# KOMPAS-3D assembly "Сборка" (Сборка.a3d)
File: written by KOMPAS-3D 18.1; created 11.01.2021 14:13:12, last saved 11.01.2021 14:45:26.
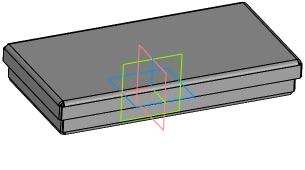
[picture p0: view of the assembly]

Document properties: Полное имя файла: D:\Ящик\Сборка.a3d

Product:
- Part/product: Сборка
    Масса: 0.773946
  - Component [detail]: Ящик  | designation 001  | Масса: 0.424246; Форматы листов документа: A3; source file: 001 - Ящик.m3d, Развертки.cdw
  - Component [detail]: Крышка  | designation 002  | Масса: 0.3497; Форматы листов документа: A3; source file: 002 - Крышка.m3d, Развертки.cdw

Referenced files in D:\Ящик\: 001 - Ящик.m3d, 002 - Крышка.m3d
